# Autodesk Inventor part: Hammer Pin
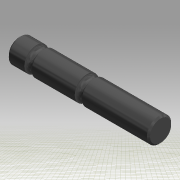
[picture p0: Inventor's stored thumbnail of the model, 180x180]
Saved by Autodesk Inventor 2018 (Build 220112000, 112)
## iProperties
Part Number: Hammer Pin
Material: SolidWorks Materials|AISI 316 Annealed Stainless Steel Bar (SS)
Document SubType Name: Modeling
Designer: johne
Density: 8 g/cm^3
Appearance: Default
Author: johne
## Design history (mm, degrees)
feature "Body1"
body "Solid1"
